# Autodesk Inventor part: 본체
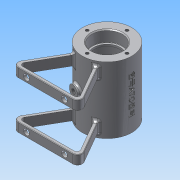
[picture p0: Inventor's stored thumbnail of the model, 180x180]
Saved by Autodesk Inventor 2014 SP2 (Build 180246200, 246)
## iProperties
Created: 2016-03
Part Number: 본체
Material: 알루미늄 6061
Document SubType Name: Modeling
Designer: 703
Density: 2.71 g/cm^3
Appearance: 알루미늄 - 평지
Mass: 211.124 g
Surface Area: 327.195 cm^2
Volume: 77.9056 cm^3
Author: 703
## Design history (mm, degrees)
sketch "스케치1"
  geometry: C1 r 26 at (0, 0); 1 further point
  constraints: 1 centre point, 1 coincident
  dimensions: "d0" = 52 diameter of C1
extrude "돌출1" new body sketch "스케치1" stored distance "d1" = 70; taper "d2" = 0 deg
sketch "스케치2"
  geometry: C1 r 21 at (0, 0); 1 further point
  constraints: 1 centre point, 1 coincident
  dimensions: "d3" = 42 diameter of C1
extrude "돌출2" cut sketch "스케치2" stored distance "d4" = 42; taper "d5" = 0 deg
hole "구멍1" diameter "d8" = 32; stored, may be unused: countersink angle "d12" = 90 deg, drill point angle "d14" = 0 deg; dims "d6" = 10, "d7" = 10, "d9" = 6, "d10" = 4, "d11" = 2, "d13" = 12
hole "구멍2" diameter "d17" = 28; stored, may be unused: countersink angle "d21" = 90 deg, drill point angle "d23" = 0 deg; dims "d15" = 10, "d16" = 10, "d18" = 6, "d19" = 4, "d20" = 2, "d22" = 2
hole "구멍3" diameter "d26" = 32; stored, may be unused: countersink angle "d30" = 90 deg, drill point angle "d32" = 0 deg; dims "d24" = 10, "d25" = 10, "d27" = 6, "d28" = 4, "d29" = 2, "d31" = 12
hole "구멍4" diameter "d35" = 28; stored, may be unused: countersink angle "d39" = 90 deg, drill point angle "d41" = 0 deg; dims "d33" = 10, "d34" = 10, "d36" = 6, "d37" = 4, "d38" = 2, "d40" = 2
node "작업 평면1"
sketch "스케치5"
  geometry: L1 (0, 0)-(0, -65); L2 (-13, -22.517)-(-37.528, -65); L3 (0, -65)-(-37.528, -65); L4 (13, -22.517)-(37.528, -65); L5 (0, -65)-(37.528, -65); L6 (10.315, -23.866)-(32.332, -62); L7 (32.332, -62)-(0, -62); L8 (-10.315, -23.866)-(-32.332, -62); L9 (-32.332, -62)-(0, -62); C1 r 16 at (0, 0) reference; A1 r 26 centre (0, 0) between (-13, -22.517) and (13, -22.517); 3 further points
  constraints: 18 end point, 4 point on circle, 4 symmetric about line, 2 point on line, 1 centre point, 1 coincident, 1 perpendicular, 1 vertical, 2 other
  dimensions: "d45" = 65 distance of L1.start L1.end; "d46" = 30 deg angle of L1 L2; "d47" = 42.48334 vertical distance of L2.end L2.start; "d48" = 3 distance between parallel lines of L4 L6; "d50" = 3 distance between parallel lines of L5 L7
extrude "돌출3" join sketch "스케치5" distance "d51" = 10; taper "d52" = 0 deg
node "작업 평면4"
sketch "스케치9"
  geometry: C1 r 5 at (0, 0); 1 further point
  constraints: 1 centre point, 1 coincident
  dimensions: "d71" = 10 diameter of C1
extrude "돌출5" join sketch "스케치9" stored distance "d72" = 3; taper "d73" = 0 deg
hole "구멍6" diameter "d76" = 5.188; stored, may be unused: countersink angle "d80" = 90 deg, drill point angle "d82" = 0 deg; dims "d77" = 10, "d78" = 4, "d79" = 2, "d81" = 10, "d85" = 10, "d86" = 10
sketch "스케치14"
  geometry: L1 (0, 0)-(0, -65); L2 (-37.528, -65)-(37.528, -65) reference; L3 (0, 0)-(-7.506, -28.012); L4 (-7.506, -28.012)-(-1.71, -29.565); L5 (-1.71, -29.565)-(-0.752, -25.989); L6 (-0.752, -25.989)-(-6.548, -24.436); C1 r 16 at (0, 0) reference; 2 further points
  constraints: 10 end point, 3 perpendicular, 1 midpoint, 1 point on line, 2 other
  dimensions: "d104" = 15 deg angle of L1 L3; "d105" = 29 distance of point (0, 0) L3.end; "d106" = 6 distance of L3.end L4.end
fillet "모깎기1" dims "d117" = 5
sketch "스케치15"
  geometry: L1 (64.663, 0)-(0, 0) reference; C1 r 3 at (12.332, -5); 1 further point
  constraints: 1 centre point
  dimensions: "d118" = 5 distance from line of L1 C1.centre; "d119" = 20 horizontal distance of point (32.332, 20) C1.centre; "d120" = 6 diameter of C1
extrude "돌출6" cut sketch "스케치15" stored distance "d121" = 3; taper "d122" = 0 deg
sketch "스케치16" dims "d123" = 42
  geometry: C1 r 26 at (0, 0) reference; 2 further points
  constraints: 2 vertical alignment, 1 coincident, 2 other
hole "구멍9" sketch "스케치16" at (0, 21) diameter "d124" = 3.242; stored, may be unused: countersink angle "d128" = 90 deg, drill point angle "d130" = 118 deg; dims "d125" = 8, "d126" = 4, "d127" = 2, "d129" = 10
fillet "모깎기2" dims "d134" = 3
fillet "모깎기3" dims "d135" = 0.3
chamfer "모따기1" distance "d136" = 1; stored, may be unused: second distance "d137" = 2, angle "d138" = 45 deg
node "작업 평면5"
sketch "스케치17"
  geometry: L1 (26, 35)-(-26, 35) reference; L2 (26, -35)-(26, 35) reference; 2 further points
  constraints: 1 other
  dimensions: "d139" = 35 distance from line of L1 point (0, 0); "d140" = 26 distance from line of L2 point (0, 0)
feature "엠보싱1" sketch "스케치17" dims "d0" = 52, "d33" = 10, "d141" = 0.5, "d142" = 0
fillet "모깎기4" dims "d143" = 3
fillet "모깎기5" dims "d144" = 0.5
fillet "모깎기6" dims "d145" = 3
revolve "회전3" stored, may be unused: angle "d146" = 90 deg
hole "구멍10" diameter "d149" = 5.188; stored, may be unused: countersink angle "d153" = 90 deg, drill point angle "d155" = 118 deg; dims "d150" = 10, "d151" = 4, "d152" = 2, "d154" = 10, "d156" = 10, "d157" = 10
fillet "모깎기7" dims "d158" = 2
node "솔리드1"
mirror "대칭1"
mirror "대칭2"
mirror "대칭3"
pattern_circular "원형 패턴1" dims angle "d132" = 360 deg
mirror "대칭4"
node "투영된 루프1"
other parameters: "d70" = 29
